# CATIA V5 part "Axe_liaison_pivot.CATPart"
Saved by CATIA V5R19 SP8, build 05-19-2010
Part number: Axe_liaison_pivot
Bounding box of the stored display mesh (mm): x -50 to 50, y -50 to 50, z 1065 to 1250
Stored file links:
  G:\EU_thinkMotion\CFAO_2010\MMS_groupe2\MMS_groupe2\OK\nrosalie\nrosalie_cfao_support_d_arme_legere_final\Axe_liaison_pivot.CATPart
  G:\EU_thinkMotion\CFAO_2010\MMS_groupe2\MMS_groupe2\OK\nrosalie\nrosalie_cfao_support_d_arme_legere_final\nrosalie_Support_d_arme_legere.CATProduct
  G:\EU_thinkMotion\CFAO_2010\MMS_groupe2\MMS_groupe2\OK\nrosalie\nrosalie_cfao_support_d_arme_legere_final\Squelette_Colone.CATPart
  G:\EU_thinkMotion\CFAO_2010\MMS_groupe2\MMS_groupe2\OK\nrosalie\nrosalie_cfao_support_d_arme_legere_final\Colonne.CATPart
  G:\EU_thinkMotion\CFAO_2010\MMS_groupe2\MMS_groupe2\OK\nrosalie\nrosalie_cfao_support_d_arme_legere_final\NKX_45_PART1.CATPart
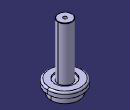
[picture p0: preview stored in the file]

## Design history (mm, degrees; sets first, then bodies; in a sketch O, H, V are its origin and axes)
Set1
  Sketch1 on DatumSurface1, origin (0, 0, 1085), H (1, 0, 0), V (0, 1, 0)
    circle A1 centre (0, 0) radius 40
    reference projected circle E1 centre (0, 0) radius 40 from edge of DatumCurve1
    coincidence: A1 E1
Set2
  Plane1 "Plan_limite_inferieur_liaison_pivot_colone_systeme": linked copy from another document
  DatumCurve1: linked copy from another document
  DatumCurve2: linked copy from another document
  Point1 "Centre_plan_limite_superieur_colonne": linked copy from another document
  Plane2 "Plan_limite_superieur_colonne": linked copy from another document
  DatumSurface1: linked copy from another document
  DatumCurve3: linked copy from another document
Body1 (main body)
  Pad1: profile Sketch1, direction (0, 0, -1), length 20
  Sketch2 on Plane1, origin (0, 0, 1100), H (1, 0, 0), V (0, 1, 0)
    circle A1 centre (0, 0) radius 50
    reference projected circle E1 centre (0, 0) radius 50 from edge of DatumCurve2
    coincidence: A1 E1
  Pad2: profile Sketch2, direction (0, 0, 1), up to start face of Pad1
  Sketch3 on Plane1, origin (0, 0, 1100), H (1, 0, 0), V (0, 1, 0)
    circle A1 centre (0, 0) radius 20
    reference projected point E1 (0, 0) from Point1
    radius A1 = 20
    concentricity: A1 E1
  Pad3: profile Sketch3, direction (0, 0, 1), up to Plane2
  Fillet1: radius 5, on edge [face of Pad2 from Sketch2.A1 | start face of Pad2]
  Chamfer1: length 1, angle 45, on end face of Pad3
  Sketch4 on end face of Pad3, origin (0, 0, 1250), H (1, 0, 0), V (0, 1, 0)
    point P1 (0, 0)
    reference projected point E1 (0, 0) from Point1
    coincidence: E1 P1
  Hole1: placed by Sketch4, at (0, 0, 1250) direction (0, 0, -1), diameter 10, depth 12, threaded, thread diameter 11, thread depth 10, pitch 1
  Sketch5 on start face of Pad2, origin (0, 0, 1100), H (1, 0, 0), V (0, 1, 0)
    circle A1 centre (0, 0) radius 28.5
    reference projected circle E1 centre (0, 0) radius 28.5 from edge of DatumCurve3
    circle A2 centre (0, 0) radius 20
    reference projected circle E2 centre (0, 0) radius 20 from edge [face of Pad3 from Sketch3.A1 | face of Chamfer1]
    coincidence: E1 A1, A2 E2
  Pocket1: profile Sketch5, direction (0, 0, -1), length 4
